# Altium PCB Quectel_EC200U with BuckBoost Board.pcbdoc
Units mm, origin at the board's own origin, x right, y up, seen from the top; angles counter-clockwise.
Board outline 58.96 x 62.7 mm, 2 copper layers (Top Layer, Bottom Layer); 75 components, 67 nets, 368 pads, 218 vias.
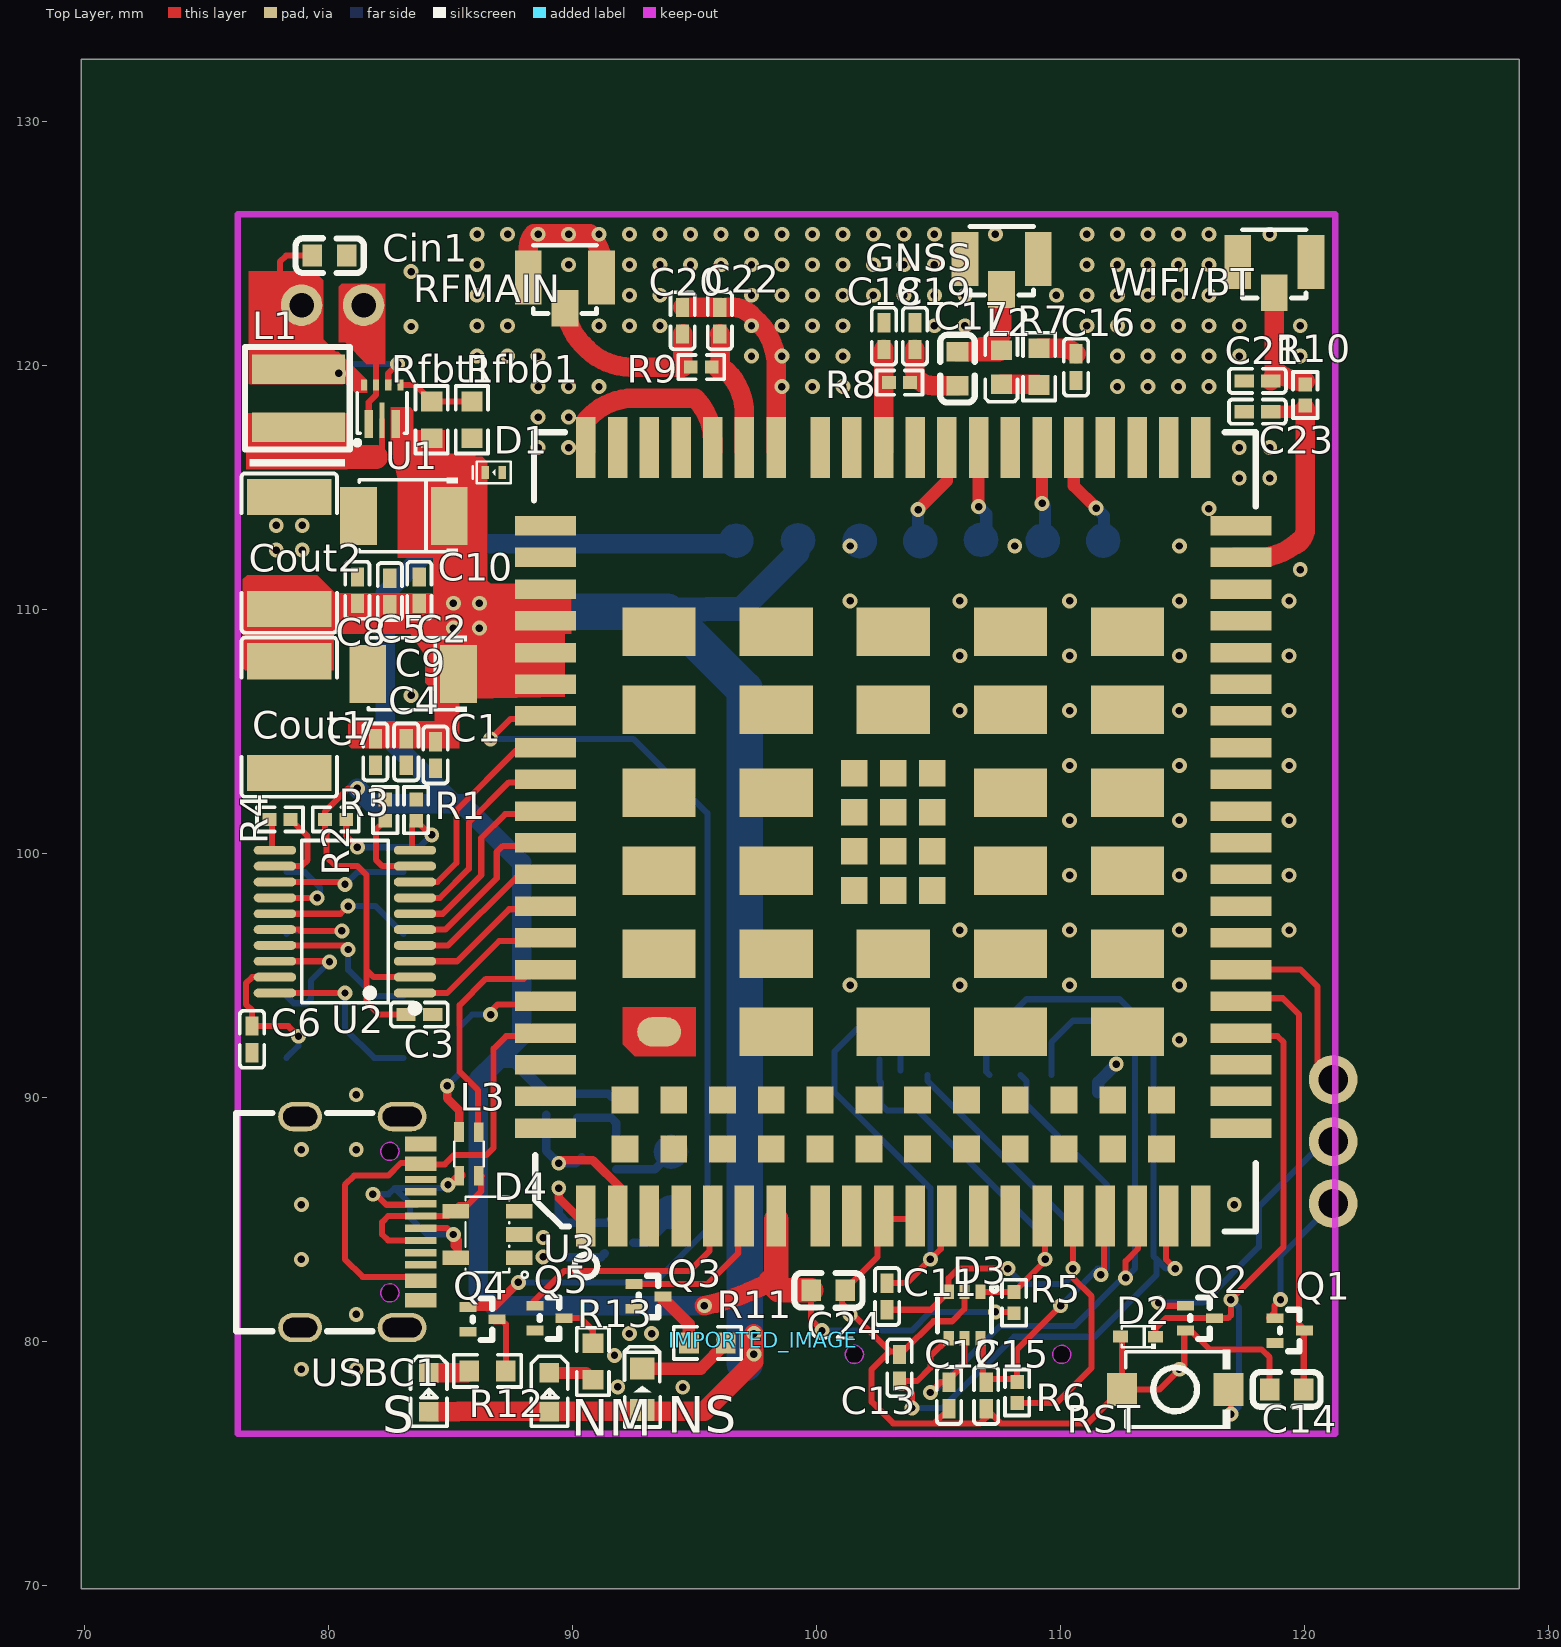
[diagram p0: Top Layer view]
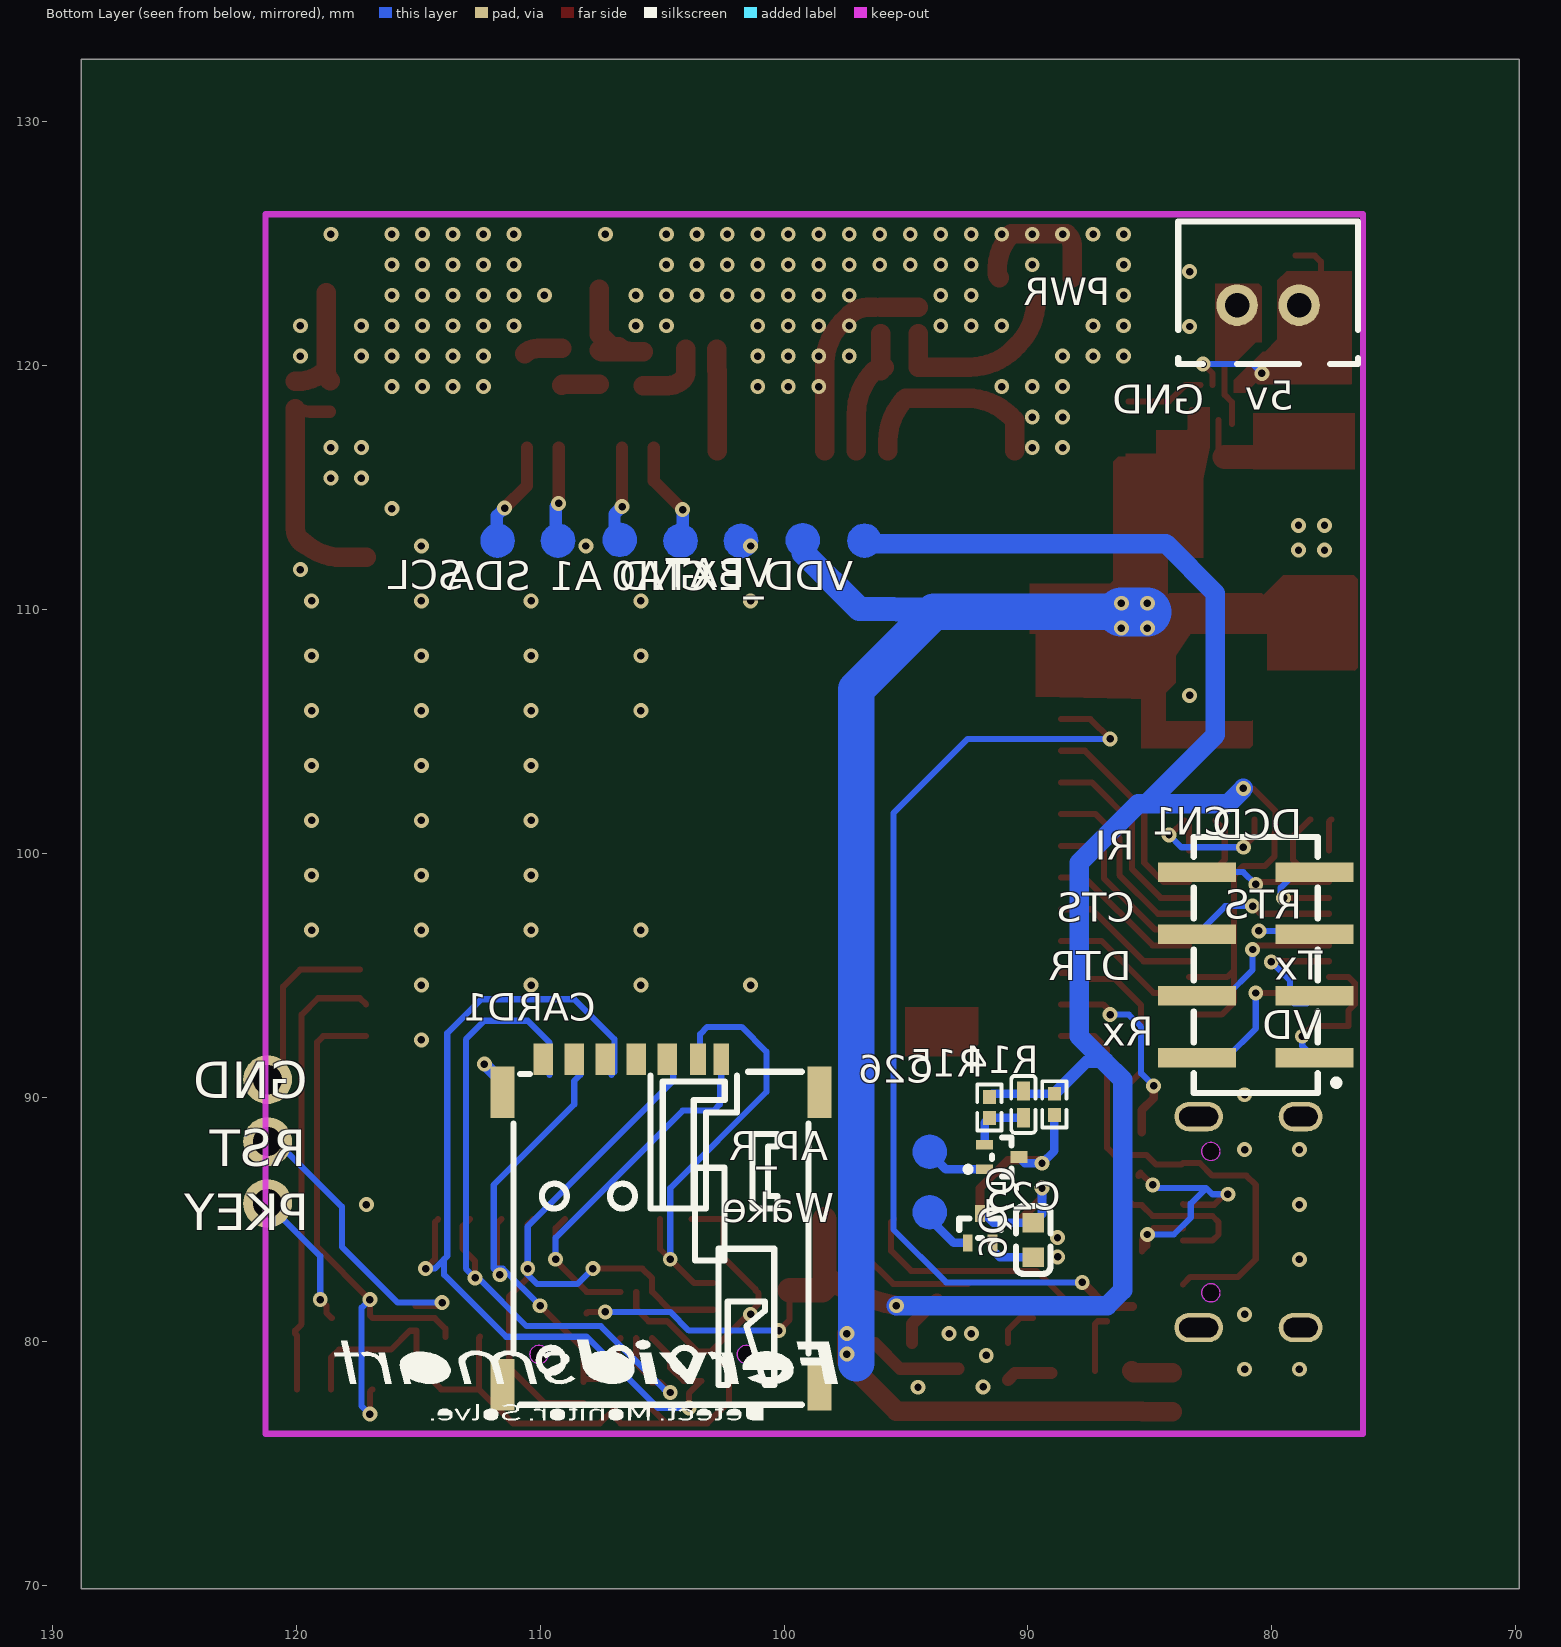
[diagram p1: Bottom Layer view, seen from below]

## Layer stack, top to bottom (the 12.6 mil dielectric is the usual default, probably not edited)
Top Layer: signal copper (thickness not stored)
Dielectric: dielectric 0.32, FR-4, Dk 4.8
Bottom Layer: signal copper (thickness not stored)

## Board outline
128.808,69.85 69.85,69.85 69.85,132.55 128.808,132.55

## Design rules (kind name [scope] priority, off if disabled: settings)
BoardOutlineClearance Default [All] p0: genericclearance=0.254 ignorepadtopadclearanceinfootprint=FALSE except(0: Arc-SplitContinuation Track-SplitContinuation SMDPad-SplitContinuation THPad-SplitContinuation Via-SplitContinuation Fill-SplitContinuation Poly-SplitContinuation Region-SplitContinuation Text-SplitContinuation; 0.152: Track-OutlineEdge SMDPad-OutlineEdge THPad-OutlineEdge Via-OutlineEdge Fill-OutlineEdge Region-OutlineEdge Poly-OutlineEdge Text-OutlineEdge Track-CutoutEdge SMDPad-CutoutEdge THPad-CutoutEdge Via-CutoutEdge Fill-CutoutEdge Region-CutoutEdge)
Clearance Default [(InNet('GND') OR InNet('VBAT') OR InNet('RSTKEY') OR InNet('PWRKEY') OR InNet('$1N59') OR InNet('RF_ANT') OR InNet('WIFI/BT_ANT') OR InNet('$1N62') OR InNet('GNSS_ANT') OR InNet('$1N42256') OR InNet('$1N42254') OR InNet('VDD_EXT') OR InNet('SIM_VDD') OR InNet('SIM_GND') OR InNet('VCC(5V)') OR InNet('WAKEUP_IN') OR InNet('AP_READY') OR InNet('PKEY') OR InNet('MCU_DTR') OR InNet('MCU_RTS') OR InNet('MCU_CTS') OR InNet('MCU_DCD') OR InNet('MCU_RI') OR InNet('$1N67') OR InNet('$3N3620') OR InNet('$3N3623') OR InNet('USB_DP') OR InNet('USB_DM') OR InNet('$1N56747') OR InNet('$3N512') OR InNet('RKEY') OR InNet('NW') OR InNet('STATUS') OR InNet('NW_MODE') OR InNet('SLEEP_IND') OR InNet('SIM_DATA') OR InNet('SIM_CLK') OR InNet('SIM_RST') OR InNet('$1N42291') OR InNet('$1N42271') OR InNet('$1N42272') OR InNet('ADC1') OR InNet('ADC0') OR InNet('I2C_SCL') OR InNet('I2C_SDA') OR InNet('$3N5937') OR InNet('$1N56691') OR InNet('MAIN_DCD') OR InNet('MAIN_RI') OR InNet('MAIN_DTR') OR InNet('MAIN_RXD') OR InNet('MAIN_TXD') OR InNet('MAIN_CTS') OR InNet('MAIN_RTS') OR InNet('MCU_TXD') OR InNet('MCU_RXD') OR InNet('MCC_VDD') OR InNet('$1N68') OR InNet('SIM_DET') OR InNet('$3N12540') OR InNet('$3N12543') OR InNet('VBUS') OR InNet('$3N13600') OR InNet('WAKEUP_IN_MCU') OR InNet('AP_READY_MCU') OR InNet('$3N15666') OR InNet('$3N15711'))] p1: gap=0.178 ignorepadtopadclearanceinfootprint=FALSE except(0: Poly-Poly; 0.152: Track-Track Track-SMDPad SMDPad-SMDPad Track-THPad SMDPad-THPad THPad-THPad Track-Via SMDPad-Via THPad-Via Via-Via Track-Fill SMDPad-Fill THPad-Fill Via-Fill Fill-Fill Track-Region SMDPad-Region THPad-Region Via-Region Fill-Region Region-Region Track-Poly SMDPad-Poly THPad-Poly Via-Poly Fill-Poly Region-Poly Track-Text SMDPad-Text THPad-Text Via-Text Fill-Text Region-Text Poly-Text Text-Text Track-Sheet SMDPad-Sheet THPad-Sheet Via-Sheet Fill-Sheet Region-Sheet Poly-Sheet Text-Sheet Track-Hole SMDPad-Hole THPad-Hole Via-Hole Fill-Hole Region-Hole Poly-Hole Text-Hole Sheet-Hole)
DiffPairsRouting differentialPair [All] p1: maxuncoupledlength=10 minlimit=5.9843 maxlimit=5.9843 mostfreqgap=5.9843 toplayer_minwidth=5 toplayer_prefwidth=10 toplayer_maxwidth=100 bottomlayer_minwidth=5 bottomlayer_prefwidth=10 bottomlayer_maxwidth=100
PasteMaskExpansion Common [All] p1: expansion=0
PlaneConnect Default [All] p1: planeconnectstyle=Relief reliefexpansion=0.508 reliefentries=4 reliefconductorwidth=0 reliefairgap=0.254
PolygonConnect copperRegion [All] p1: connectstyle=Direct reliefentries=4 reliefconductorwidth=10 polygonreliefangle="90 Angle" airgapwidth=10
PolygonConnect RF_copperRegion [All] p1: connectstyle=Direct reliefentries=4 reliefconductorwidth=10 polygonreliefangle="90 Angle" airgapwidth=10
RoutingVias Default [All] p1: viastyle="Through Hole" holewidth=12.0078 minholewidth=12.0078 maxholewidth=2362.0078 width=24.0158 minwidth=24.0158 maxwidth=3937.9922
SolderMaskExpansion Common [All] p1: useseparateexpansions=TRUE expansion=2.0079 expansionbottom=2.0079
Width Default [All] p1: maxlimit=236 minlimit=8 preferedwidth=10

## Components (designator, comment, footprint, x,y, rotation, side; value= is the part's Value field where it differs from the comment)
C1 "" C0402 84.369,104.03 r270 top
C2 "" C0402 83.707,110.786 r90 top
C3 "" C0402 83.707,93.387 r180 top
C4 "" C0402 83.172,104.155 r270 top
C5 "" C0402 82.498,110.733 r90 top
C6 "" C0402 76.849,92.371 r270 top
C7 "" C0402 81.904,104.155 r270 top
C8 "" C0402 81.167,110.786 r90 top
C9 "" CASE-B_3528 83.453,107.357 r180 top
C10 "" CASE-B_3528 83.072,113.834 r180 top
C11 "" C0402 102.884,81.83 r90 top
C12 "" C0402 105.424,77.766 r90 top
C13 "" C0402 103.392,78.909 r270 top
C14 "" C0603 119.267,78.02 r0 top
C15 "" C0402 106.948,77.766 r90 top
C16 "" C0402 110.631,119.93 r90 top
C17 "" C0603 105.77,119.867 r270 top
C18 "" C0402 102.757,121.2 r90 top
C19 "" C0402 104.027,121.2 r90 top
C20 "" C0402 94.502,121.835 r270 top
C21 "" C0402 118.068,119.369 r0 top
C22 "" C0402 96.026,121.835 r270 top
C23 "" C0402 118.068,118.104 r0 top
C24 "" C0603 100.471,82.084 r180 top
C25 "" C0603 89.781,84.145 r90 bottom
C26 "" C0402 90.184,89.704 r270 bottom
CARD1 "" SIM-SMD_SMN-303 105.043,84.878 r180 bottom
Cin1 "" C0603 80.024,124.502 r180 top
CN1 "" HDR-SMD_8P-P2.54-V-F-R2-C4-S7.1 80.659,95.419 r90 bottom
Cout1 "" C1812 78.373,105.579 r90 top
Cout2 "" C1812 78.373,112.31 r270 top
D1 "" X2SON-2_L1.0-W0.6-P0.70-RD 86.755,115.612 r0 top
D2 "" SOD-523F_L1.2-W0.8-LS1.7-RD 113.171,80.179 r180 top
D3 "" SC-70-6_L2.2-W1.3-P0.65-LS2.1-BR 106.059,81.068 r90 top
D4 "" SOT-23-5_L3.0-W1.7-P0.95-LS2.8-BR 86.501,84.37 r0 top
GNSS "" ANT-SMD_UFL-R-SMT-1-10 107.583,123.74 r90 top
IMPORTED_IMAGE "IMPORTED_IMAGE" IMPORTED_IMAGE 97.804,80.052 r0 top
L1 "" IND-SMD_L4.0-W4.0_XFL4020-102MEB 78.754,118.66 r270 top
L2 "47nH" IND-SMD_L1.6-W0.8-1 107.583,119.93 r90 top
L3 "" IND-SMD_4P-L2.0-W1.2-TL 85.739,87.672 r90 top
NM "" LED0603-RD 89.041,77.893 r270 top
NS "LED-0603_G" LED0603_GREEN 92.851,78.02 r90 top
PWR "" CONN-TH_B2B-XH-A-LF-SN 80.151,122.47 r180 bottom
Q1 "" SOT-416_L1.6-W0.8-P1.00-LS1.6-BR 119.394,80.433 r180 top
Q2 "" SOT-416_L1.6-W0.8-P1.00-LS1.6-BR 115.711,80.941 r180 top
Q3 "" SOT-416_L1.6-W0.8-P1.00-LS1.6-BR 93.105,81.83 r180 top
Q4 "" SOT-416_L1.6-W0.8-P1.00-LS1.6-BR 86.294,80.891 r180 top
Q5 "" SOT-416_L1.6-W0.8-P1.00-LS1.6-BR 89.041,80.941 r180 top
Q6 "" SOT-416_L1.6-W0.8-P1.00-LS1.6-BR 91.962,84.624 r270 bottom
Q7 "" SOT-416F_L1.6-W0.8-P1.00-LS1.6-TR 91.073,87.545 r0 bottom
R1 "" R0402 83.58,101.769 r90 top
R2 "" R0402 80.278,101.388 r180 top
R3 "" R0402 82.31,101.769 r270 top
R4 "" R0402 77.992,101.388 r180 top
R5 "" R0402 108.091,81.576 r90 top
R6 "" R0402 108.218,77.893 r90 top
R7 "" R0603 109.115,119.95 r270 top
R8 "" R0402 103.392,119.295 r180 top
R9 "" R0402 95.264,119.93 r180 top
R10 "" R0402 120.029,118.787 r90 top
R11 "100Ω" R0603 95.518,79.925 r180 top
R12 "100Ω" R0603 86.501,78.782 r0 top
R13 "" R0603 90.819,79.163 r270 top
R14 "" R0402 88.914,89.704 r90 bottom
R15 "" R0402 91.581,89.577 r270 bottom
Rfbb1 "" R0603 85.866,117.771 r90 top
Rfbt1 "" R0603 84.215,117.771 r270 top
RFMAIN "" ANT-SMD_UFL-R-SMT-1-10 89.676,122.978 r90 top
RST "" SW-SMD_L3.9-W3.0-P4.45 114.695,78.02 r0 top
S "" LED0603-RD 84.088,77.893 r270 top
U1 "" VQFN-7_L2.0-W2.0-P0.55-TL_RWU 82.183,118.406 r90 top
U2 "" TSSOP-20_L6.5-W4.4-P0.65-LS6.4-BL 80.659,97.197 r90 top
U3 "" LCC-LGA-144_L32.0-W29.0-CAT1-CUIOT-MZ-6 103.138,100.88 r90 top
USBC1 "" USB-C_SMD-TYPE-C-31-M-12 81.294,84.878 r270 top
WIFI/BT "" ANT-SMD_UFL-R-SMT-1-10 118.759,123.613 r90 top

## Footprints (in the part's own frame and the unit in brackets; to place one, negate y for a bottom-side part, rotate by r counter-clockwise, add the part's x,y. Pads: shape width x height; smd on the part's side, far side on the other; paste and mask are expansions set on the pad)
ANT-SMD_UFL-R-SMT-1-10 [mm]
  rect 2.2x1.1 smd: 1(0.625,1.5) 3(0.625,-1.5)
  rect 1.5x1.1 smd: 2(-0.625,0.001)
  silkscreen extent -0.85,-1.3 1.95,1.3
C0402 [mm]
  rect 0.79x0.54 smd: 1(-0.545,0) 2(0.545,0)
  silkscreen extent -1.17,-0.5 1.17,0.5
C0603 [mm]
  rect 0.8x0.9 smd: 1(-0.7,0) 2(0.7,0)
  silkscreen extent -1.39,-0.71 1.39,0.71
C1812 [mm]
  rect 1.485x3.456 smd: 1(-2.293,0) 2(2.293,0)
  silkscreen extent -3.26,-1.96 3.26,1.96
CASE-B_3528 [mm]
  rect 1.506x2.376 smd: 1(-1.861,0) 2(1.861,0)
  silkscreen extent -2.21,-1.55 1.83,1.55
CONN-TH_B2B-XH-A-LF-SN [mm]
  round 1.7 hole 1: 1(1.27,0) 2(-1.27,0)
  silkscreen extent -3.68,-2.41 3.68,3.43
HDR-SMD_8P-P2.54-V-F-R2-C4-S7.1 [mm]
  rect 0.8x3.2 smd: 1(-3.81,-2.4) 2(-3.81,2.4) 3(-1.27,-2.4) 4(-1.27,2.4) 5(1.27,-2.4) 6(1.27,2.4) 7(3.81,-2.4) 8(3.81,2.4)
  silkscreen extent -5.25,-3.43 5.25,2.54
IMPORTED_IMAGE [mm]
IND-SMD_4P-L2.0-W1.2-TL [mm]
  rect 0.8x0.4 smd: 1(-0.901,0.399) 2(-0.899,-0.4) 3(0.9,-0.4) 4(0.901,0.4)
  silkscreen extent -0.5,-0.6 0.5,0.6
IND-SMD_L1.6-W0.8-1 [mm]
  rect 0.8x0.864 smd: 1(0.7,0) 2(-0.7,0)
  silkscreen extent -1.42,-0.65 1.41,0.67
IND-SMD_L4.0-W4.0_XFL4020-102MEB [mm]
  rect 1.2x3.8 smd: 1(-1.189,0) 2(1.189,0)
  silkscreen extent -2.1,-2.2 2.8,2.1
LCC-LGA-144_L32.0-W29.0-CAT1-CUIOT-MZ-6 [mm]
  rect 2.5x0.8 smd: 1(-15.75,12.6) 2(-15.75,11.3) 3(-15.75,10) 4(-15.75,8.7) 5(-15.75,7.4) 6(-15.75,6.1) 7(-15.75,4.8) 8(-15.75,0.4) 9(-15.75,-0.9) 10(-15.75,-2.2) 11(-15.75,-3.5) 12(-15.75,-4.8) 13(-15.75,-6.1) 14(-15.75,-7.4) 15(-15.75,-8.7) 16(-15.75,-10) 17(-15.75,-11.3) 18(-15.75,-12.6) 37(15.75,-12.6) 38(15.75,-11.3) 39(15.75,-10) 40(15.75,-8.7) 41(15.75,-7.4) 42(15.75,-6.1) 43(15.75,-4.8) 44(15.75,-3.5) 45(15.75,-2.2) 46(15.75,-0.9) 47(15.75,0.4) 48(15.75,4.8) 49(15.75,6.1) 50(15.75,7.4) 51(15.75,8.7) 52(15.75,10) 53(15.75,11.3) 54(15.75,12.6) 141(-15.75,3) 142(-15.75,1.7) 143(15.75,1.7) 144(15.75,3)
  rect 0.8x2.5 smd: 19(-9.55,-14.25) 20(-8.25,-14.25) 21(-6.95,-14.25) 22(-5.65,-14.25) 23(-4.35,-14.25) 24(-3.05,-14.25) 25(-1.75,-14.25) 26(-0.45,-14.25) 27(0.85,-14.25) 28(2.15,-14.25) 29(3.45,-14.25) 30(4.75,-14.25) 31(6.05,-14.25) 32(7.35,-14.25) 33(8.65,-14.25) 34(9.95,-14.25) 35(11.25,-14.25) 36(12.55,-14.25) 55(12.55,14.25) 56(11.25,14.25) 57(9.95,14.25) 58(8.65,14.25) 59(7.35,14.25) 60(6.05,14.25) 61(4.75,14.25) 62(3.45,14.25) 63(2.15,14.25) 64(0.85,14.25) 65(-0.45,14.25) 66(-1.75,14.25) 67(-3.05,14.25) 68(-4.35,14.25) 69(-5.65,14.25) 70(-6.95,14.25) 71(-8.25,14.25) 72(-9.55,14.25) 113(-10.85,14.25) 114(-12.15,14.25) 115(-10.85,-14.25) 116(-12.15,-14.25)
  rect 1.1x1.1 smd: 73(2.4,1.6) 74(2.4,0) 75(2.4,-1.6) 76(0.8,1.6) 77(0.8,0) 78(0.8,-1.6) 79(-0.8,1.6) 80(-0.8,0) 81(-0.8,-1.6) 82(-2.4,1.6) 83(-2.4,0) 84(-2.4,-1.6) 117(-11,11) 118(-11,9) 119(-11,7) 120(-11,5) 121(-11,3) 122(-11,1) 123(-11,-1) 124(-11,-3) 125(-11,-5) 126(-11,-7) 127(-11,-9) 128(-11,-11) 129(-13,11) 130(-13,9) 131(-13,7) 132(-13,5) 133(-13,3) 134(-13,1) 135(-13,-1) 136(-13,-3) 137(-13,-5) 138(-13,-7) 139(-13,-9) 140(-13,-11)
  rect 2x3 smd: 85(8.2,9.6) 86(8.2,4.8) 87(8.2,0) 88(8.2,-4.8) 89(8.2,-9.6) 90(5,9.6) 91(5,4.8) 92(5,0) 93(5,-4.8) 94(5,-9.6) 95(1.6,9.6) 96(1.6,4.8) 97(1.6,-4.8) 98(1.6,-9.6) 99(-1.6,9.6) 100(-1.6,4.8) 101(-1.6,-4.8) 102(-1.6,-9.6) 103(-5,9.6) 104(-5,4.8) 105(-5,0) 106(-5,-4.8) 107(-5,-9.6) 109(-8.2,4.8) 110(-8.2,0) 111(-8.2,-4.8) 112(-8.2,-9.6)
  oval 1.2x1.8 smd: 108(-8.2,9.6)
  Top Layer region: -9.2,8.1 -7.2,8.1 -7.2,11.1 -8.7,11.1 -9.2,10.6
  silkscreen extent -18.26,-14.86 16.38,14.73
LED0603-RD [mm]
  rect 0.8x0.8 smd: 1(-0.799,0) 2(0.799,0)
  silkscreen extent -1.49,-0.75 1.39,0.76
LED0603_GREEN [mm]
  rect 0.9x1 smd: 1(-0.85,0) 2(0.85,0)
  silkscreen extent -1.54,-0.73 1.75,0.73
R0402 [mm]
  rect 0.566x0.54 smd: 1(-0.433,0) 2(0.433,0)
  silkscreen extent -0.94,-0.5 0.94,0.5
R0603 [mm]
  rect 0.806x0.864 smd: 1(-0.753,0) 2(0.753,0)
  silkscreen extent -1.39,-0.66 1.39,0.66
SC-70-6_L2.2-W1.3-P0.65-LS2.1-BR [mm]
  rect 0.6x0.42 smd: 1(0.95,-0.65) 2(0.95,0) 3(0.95,0.65) 4(-0.95,0.65) 5(-0.95,0) 6(-0.95,-0.65)
  silkscreen extent -0.7,-1.34 1.22,1.1
SIM-SMD_SMN-303 [mm]
  rect 1x2.1 smd: 8(-6.5,5.328) 9(6.5,5.328) 10(6.5,-6.672) 11(-6.5,-6.672)
  rect 0.8x1.3 smd: C1(0.25,6.672) C2(-2.29,6.672) C3(-4.83,6.672) C6(-1.02,6.672) C7(-3.56,6.672)
  rect 0.65x1.3 smd: C5(1.52,6.672) CD(2.47,6.672)
  Board Outline Layer circle w0.005: c-5,-5.422 r0.375
  Board Outline Layer circle w0.005: c3.5,-5.422 r0.375
  Board Outline Layer region: -5.375,-5.422 -5.338,-5.585 -5.234,-5.715 -5.083,-5.788 -4.916,-5.788 -4.766,-5.715 -4.662,-5.585 -4.625,-5.422 -4.625,-5.422 -4.662,-5.259 -4.766,-5.129 -4.916,-5.057 -5.083,-5.057 -5.234,-5.129 -5.338,-5.259 -5.375,-5.422
  Board Outline Layer region: 3.125,-5.422 3.162,-5.585 3.266,-5.715 3.417,-5.788 3.583,-5.788 3.734,-5.715 3.838,-5.585 3.875,-5.422 3.875,-5.422 3.838,-5.259 3.734,-5.129 3.583,-5.057 3.417,-5.057 3.266,-5.129 3.162,-5.259 3.125,-5.422
  Multi-Layer board cut-out: -5.375,-5.422 -5.338,-5.585 -5.234,-5.715 -5.083,-5.788 -4.916,-5.788 -4.766,-5.715 -4.662,-5.585 -4.625,-5.422 -4.625,-5.422 -4.662,-5.259 -4.766,-5.129 -4.916,-5.057 -5.083,-5.057 -5.234,-5.129 -5.338,-5.259 -5.375,-5.422
  Multi-Layer board cut-out: 3.125,-5.422 3.162,-5.585 3.266,-5.715 3.417,-5.788 3.583,-5.788 3.734,-5.715 3.838,-5.585 3.875,-5.422 3.875,-5.422 3.838,-5.259 3.734,-5.129 3.583,-5.057 3.417,-5.057 3.266,-5.129 3.162,-5.259 3.125,-5.422
  silkscreen extent -6.04,-7.49 6.04,6.16
SOD-523F_L1.2-W0.8-LS1.7-RD [mil]
  rect 24x19 smd: 1(-28,0.2) 2(28,-0.2)
  silkscreen extent -29,-19 26,19
SOT-23-5_L3.0-W1.7-P0.95-LS2.8-BR [mm]
  rect 1.1x0.6 smd: 1(1.3,-0.95) 2(1.3,0) 3(1.3,0.95) 4(-1.3,0.95) 5(-1.3,-0.95)
  silkscreen extent -0.9,-1.78 1.65,1.55
SOT-416_L1.6-W0.8-P1.00-LS1.6-BR [mm]
  rect 0.7x0.4 smd: 1(0.6,-0.508) 2(0.6,0.508) 3(-0.6,0)
  silkscreen extent -0.4,-0.85 0.4,0.85
SOT-416F_L1.6-W0.8-P1.00-LS1.6-TR [mm]
  rect 0.7x0.4 smd: 1(0.7,0.5) 2(0.7,-0.5)
  rect 0.7x0.5 smd: 3(-0.7,0)
  silkscreen extent -0.4,-0.8 1.48,0.8
SW-SMD_L3.9-W3.0-P4.45 [mm]
  rect 1.23x1.36 smd: 1(-2.185,0) 2(2.185,0)
  silkscreen extent -2.03,-1.62 2.25,1.62
TSSOP-20_L6.5-W4.4-P0.65-LS6.4-BL [mm]
  oval 0.364x1.742 smd: 1(-2.925,-2.871) 2(-2.275,-2.871) 3(-1.625,-2.871) 4(-0.975,-2.871) 5(-0.325,-2.871) 6(0.325,-2.871) 7(0.975,-2.871) 8(1.625,-2.871) 9(2.275,-2.871) 10(2.925,-2.871) 11(2.925,2.871) 12(2.275,2.871) 13(1.625,2.871) 14(0.975,2.871) 15(0.325,2.871) 16(-0.325,2.871) 17(-0.975,2.871) 18(-1.625,2.871) 19(-2.275,2.871) 20(-2.925,2.871)
  silkscreen extent -3.71,-3.02 3.33,1.77
USB-C_SMD-TYPE-C-31-M-12 [mm]
  oval 1.2x2 hole 0.8 slot 1.6 at 90 deg: 0(-4.325,1.706) 1(4.325,1.706)
  oval 1.2x1.8 hole 0.8 slot 1.4 at 90 deg: 2(4.325,-2.474) 3(-4.325,-2.474)
  rect 0.3x1.3 smd: A1(-3.35,2.474) A4(-2.55,2.474) A5(-1.25,2.474) A6(-0.25,2.474) A7(0.25,2.474) A8(1.25,2.474) A9(2.55,2.474) A12(3.35,2.474) B1(3.05,2.474) B4(2.25,2.474) B5(1.75,2.474) B6(0.75,2.474) B7(-0.75,2.474) B8(-1.75,2.474) B9(-2.25,2.474) B12(-3.05,2.474)
  Board Outline Layer circle w0.005: c-2.9,1.206 r0.375
  Board Outline Layer circle w0.005: c2.9,1.206 r0.375
  Board Outline Layer region: -2.9,1.581 -2.737,1.544 -2.607,1.439 -2.534,1.289 -2.534,1.122 -2.607,0.972 -2.737,0.868 -2.9,0.831 -2.9,0.831 -3.063,0.868 -3.193,0.972 -3.266,1.122 -3.266,1.289 -3.193,1.439 -3.063,1.544 -2.9,1.581
  Board Outline Layer region: 2.9,1.581 3.063,1.544 3.193,1.439 3.266,1.289 3.266,1.122 3.193,0.972 3.063,0.868 2.9,0.831 2.9,0.831 2.737,0.868 2.607,0.972 2.534,1.122 2.534,1.289 2.607,1.439 2.737,1.544 2.9,1.581
  Multi-Layer board cut-out: -2.9,1.581 -2.737,1.544 -2.607,1.439 -2.534,1.289 -2.534,1.122 -2.607,0.972 -2.737,0.868 -2.9,0.831 -2.9,0.831 -3.063,0.868 -3.193,0.972 -3.266,1.122 -3.266,1.289 -3.193,1.439 -3.063,1.544 -2.9,1.581
  Multi-Layer board cut-out: 2.9,1.581 3.063,1.544 3.193,1.439 3.266,1.289 3.266,1.122 3.193,0.972 3.063,0.868 2.9,0.831 2.9,0.831 2.737,0.868 2.607,0.972 2.534,1.122 2.534,1.289 2.607,1.439 2.737,1.544 2.9,1.581
  silkscreen extent -4.47,-5.09 4.47,0.49
VQFN-7_L2.0-W2.0-P0.55-TL_RWU [mm]
  rect 1.15x0.35 smd: 1(-0.8,0.55) 3(-0.8,-0.55)
  rect 1.45x0.2 smd: 2(-0.65,0)
  rect 0.45x0.25 smd: 4(0.8,-0.75) 5(0.8,-0.25) 6(0.8,0.25) 7(0.8,0.75)
  silkscreen extent -1.67,-1.02 0.46,1.12
X2SON-2_L1.0-W0.6-P0.70-RD [mm]
  rect 0.3x0.55 smd: 1(-0.35,0) 2(0.35,0)
  silkscreen extent -0.85,-0.45 0.7,0.45

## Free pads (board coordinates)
  round 2 hole 1.2: 1(121.172,85.64) 1(121.172,88.18) 1(121.172,90.72)

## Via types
v1: diameter 0.61, hole 0.305, Top Layer to Bottom Layer, 218 vias

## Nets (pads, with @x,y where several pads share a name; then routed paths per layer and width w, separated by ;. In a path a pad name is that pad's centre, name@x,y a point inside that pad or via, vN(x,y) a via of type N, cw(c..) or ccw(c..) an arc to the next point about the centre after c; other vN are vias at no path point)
$1N59: C20.2 R9.2 RFMAIN.2 | length 7.7
  Top Layer w0.8: RFMAIN.2@89.675,122.634 ccw(c92.215,122.634) 90.419,120.838 90.583,120.674 ccw(c92.379,122.47) 92.379,119.93 94.502,119.93 C20.2
$1N62: C21.2 R10.2 WIFI/BT.2 | length 5.1
  Top Layer w0.8: C21.2 ccw(c118.262,119.719) 118.758,119.719 118.758,119.846 ; WIFI/BT.2 118.758,119.846 ; R10.2@120.029,119.347 119.964,119.347 cw(c119.964,121.052) 118.846,119.764 cw(c119.964,121.052) 118.758,119.846
$1N67: L2.2 R7.2 | length 1.5
  Top Layer w0.8: L2.2 109.034,119.23 cw(c109.034,119.115) R7.2
$1N68: C16.2 R7.1 | length 1.6
  Top Layer w0.8: R7.1 110.081,120.703 cw(c110.081,119.925) C16.2
$1N42254: C17.1 GNSS.2 L2.1 | length 5.2
  Top Layer w0.8: C17.1 106.28,120.567 ; GNSS.2 cw(c107.579,123.112) 107.583,123.112 107.583,121.283 107.071,120.772 106.774,120.772 cw(c106.28,121.266) 106.28,120.567 ; L2.1 cw(c107.432,120.781) 107.432,120.567 106.28,120.567
$1N42256: C17.2 C19.1 R8.1 | length 2.9
  Top Layer w0.8: C19.1 104.027,119.729 ccw(c104.461,119.729) 104.102,119.484 ccw(c104.461,119.729) 104.154,119.422 ccw(c104.767,120.035) 104.767,119.168 C17.2@105.768,119.168
$1N42271: R3.2 U2.9 | length 3.3
  Top Layer w0.25: R3.2 81.929,100.955 81.929,99.737 82.194,99.472 U2.9@83.403,99.472
$1N42272: R4.1 U2.12 | length 3.5
  Top Layer w0.25: U2.12@77.661,99.472 78.874,99.472 79.124,99.722 79.124,100.689 R4.1
$1N42291: R1.1 R2.1 U2.10 | length 6.8
  Top Layer w0.25: R2.1 80.711,100.701 v1(81.167,100.245) ; U2.10@83.403,100.122 83.403,101.159 R1.1 84.163,100.753 v1(84.215,100.753)
  Bottom Layer w0.25: v1(81.167,100.245) 83.707,100.245 v1(84.215,100.753)
$1N56691: Rfbb1.2 Rfbt1.1 U1.4 | length 3.2
  Top Layer w0.25: U1.4 83.533,119.206 Rfbt1.1 Rfbb1.2
$1N56747: L1.2 U1.2 | length 5.3
  Top Layer w0.25: 81.929,116.247 82.183,116.501 U1.2
  Top Layer w1: L1.2 79.978,116.247 81.929,116.247
$3N512: R12.1 S.1 | length 1.7
  Top Layer w0.8: S.1 85.658,78.692 R12.1
$3N3620: D4.5 L3.1 USBC1.A7 USBC1.B7 | length 12.8
  Top Layer w0.25: v1(81.802,86.021) 81.929,86.021 82.36,85.59 83.603,85.59 USBC1.B7@83.641,85.628 ; USBC1.A7@83.641,84.628 84.846,84.628 v1(85.104,84.37) ; v1(84.882,86.402) 85.386,86.906 85.467,86.825 L3.1@85.467,86.771 ; v1(85.104,84.37) 85.104,83.898 85.328,83.674 85.328,84.146 v1(85.104,84.37)
  Bottom Layer w0.25: v1(81.802,86.021) 82.437,86.021 82.691,86.275 ; v1(84.882,86.402) 84.755,86.275 82.691,86.275 ; v1(85.104,84.37) 84.017,84.37 83.326,85.061 83.326,85.64 82.691,86.275
$3N3623: D4.4 L3.2 USBC1.A6 USBC1.B6 | length 7.3
  Top Layer w0.25: USBC1.B6@83.641,84.128 82.425,84.128 82.183,84.37 82.183,84.878 82.433,85.128 USBC1.A6 84.882,85.128 85.328,85.574 85.673,85.574 86.247,86.148 86.247,86.754 L3.2@86.266,86.773
$3N5937: NM.1 R13.2 | length 1.9
  Top Layer w0.5: NM.1 90.536,78.692 R13.2
$3N12540: NS.2 R11.1 | length 3.9
  Top Layer w0.5: NS.2 95.245,78.87 96.271,79.896 R11.1
$3N12543: Q3.3 R11.2 | length 2.2
  Top Layer w0.5: Q3.3@93.705,81.703 93.749,81.703 94.756,80.696 R11.2@94.756,79.916
$3N13600: C26.2 Q7.2 R15.2 | length 2.6
  Bottom Layer w0.35: C26.2 91.566,89.159 R15.2 91.773,88.952 Q7.2
$3N15666: Q4.3 R12.2 | length 2.5
  Top Layer w0.25: Q4.3@86.764,80.814 87.136,80.814 87.254,80.696 R12.2
$3N15711: Q5.3 R13.1 | length 1.8
  Top Layer w0.25: Q5.3@89.794,80.941 90.326,80.941 90.819,80.448 R13.1
ADC0: U3.45 | length 4.6
  Top Layer w0.5: v1(104.154,114.088) 105.338,115.272 U3.45
  Bottom Layer w0.5: 104.154,112.564 v1(104.154,114.088)
ADC1: U3.44 | length 3.9
  Top Layer w0.5: v1(106.638,114.215) U3.44
  Bottom Layer w0.5: v1(106.638,114.215) 106.948,113.905 106.948,112.818
AP_READY: Q7.3 R14.1 U3.2 | length 7.7
  Top Layer w0.35: v1(89.422,87.291) 89.549,87.418 90.819,87.418 91.965,86.272 91.965,85.384 U3.2@91.584,85.003
  Bottom Layer w0.35: R14.1 88.914,87.799 v1(89.422,87.291) 90.119,87.291 Q7.3
AP_READY_MCU: Q7.1 | length 2.5
  Bottom Layer w0.35: Q7.1 93.367,87.045 93.994,87.672
GND: C1.2 C2.2 C3.1 C4.2 C5.2 C6.2 C7.2 C8.2 C9.2 C10.2 C12.1 C13.1 C14.1 C15.1 C16.1 C18.2 C19.2 C20.1 C21.1 C22.1 C23.1 C24.1 C25.1 CARD1.8 CARD1.9 CARD1.10 CARD1.11 Cin1.1 Cout1.1 Cout2.1 D1.2 D2.2 D3.2 D4.1 D4.2 D4.3 GNSS.1 GNSS.3 pad.1@121.172,90.72 PWR.2 Q1.2 Q2.2 Q3.2 Q4.2 Q5.2 Q6.2 R1.2 R3.1 R4.2 Rfbb1.1 RFMAIN.1 RFMAIN.3 RST.1 U1.1 U1.6 U2.11 U3.8 U3.9 U3.19 U3.22 U3.36 U3.46 U3.48 U3.50 U3.51 U3.52 U3.53 U3.54 U3.56 U3.72 U3.76 U3.85 U3.86 U3.87 U3.88 U3.89 U3.90 U3.91 U3.92 U3.93 U3.94 U3.95 U3.96 U3.97 U3.98 U3.99 U3.100 U3.101 U3.102 U3.103 U3.104 U3.105 U3.106 U3.107 U3.108 U3.109 U3.110 U3.111 U3.112 USBC1.A1 USBC1.A12 USBC1.B1 USBC1.B12 WIFI/BT.1 WIFI/BT.3 | length 79.6
  Top Layer w0.25: R4.2 77.661,101.286 U2.11@77.661,100.122 ; PWR.2 81.933,121.958 U1.6 81.933,118.791 81.633,118.491 U1.1 ; C13.1 C13.1@103.392,79.579 ; U3.9@103.784,85.003 102.484,85.003 102.484,83.447 101.171,82.134 C24.1 101.044,81.957 101.044,81.526 102.991,79.579 ; C12.1 104.826,76.623 ; D3.2 106.059,81.322 105.551,80.814 104.789,80.814 103.554,79.579 C13.1@103.392,79.579 ; D2.2 112.51,80.134 RST.1 ; U3.22 119.837,95.23 120.537,94.53 120.537,91.355 120.984,90.908 pad.1@120.984,90.72 ; C14.1 118.567,79.331 118.242,79.656 116.107,79.656 115.339,80.424 115.067,80.424 115.067,79.027 114.06,78.02 RST.1 ; 102.991,79.579 C13.1@103.392,79.579 ; 102.991,79.579 102.249,78.837 102.249,77.512 103.138,76.623 104.826,76.623 ; 104.826,76.623 106.698,76.623 106.948,76.873 C15.1 107.546,76.623 111.113,76.623 RST.1
  Top Layer w0.8: RFMAIN.1 88.176,124.836 cw(c88.961,124.836) 88.249,125.167 cw(c88.961,124.836) 88.406,125.391 90.692,125.391 cw(c89.054,123.913) 90.786,125.279 cw(c89.054,123.913) 90.84,125.209 cw(c89.054,123.913) 91.258,123.8 cw(c90.979,123.8) RFMAIN.3 ; U3.54@90.538,116.503 90.538,117.705 cw(c90.631,117.705) 90.565,117.771 90.71,117.916 cw(c92.506,116.12) 90.94,118.12 cw(c92.506,116.12) 91.768,118.55 cw(c92.506,116.12) 92.506,118.66 95.01,118.66 cw(c93.253,116.903) 95.148,118.511 cw(c93.253,116.903) 95.738,116.903 U3.50@95.738,116.503 ; C20.1 C22.1 ; C22.1@96.28,122.38 96.593,122.38 cw(c96.593,121.386) 97.296,122.089 97.594,121.791 cw(c95.798,119.995) 97.623,121.762 cw(c95.798,119.995) 97.992,121.275 cw(c95.798,119.995) 98.183,120.867 cw(c95.798,119.995) 98.296,120.455 cw(c95.798,119.995) 98.311,120.361 cw(c95.798,119.995) 98.338,119.995 U3.48@98.338,116.503
  Bottom Layer w0.35: C25.1 91.158,83.445 91.312,83.599
  Bottom Layer w0.5: CARD1.8 111.543,90.616 v1(112.282,91.355)
  other v1: 94.506,78.106 91.84,78.125 78.869,78.848 81.119,78.848 114.869,78.848 91.708,79.417 92.32,80.306 93.232,80.306 81.119,81.098 101.369,81.098 78.869,83.348 88.78,83.449 88.787,84.243 78.869,85.598 117.119,85.598 78.869,87.848 81.119,87.848 81.119,90.098 114.869,92.348 101.369,94.598 105.869,94.598 110.369,94.598 114.869,94.598 105.869,96.848 110.369,96.848 114.869,96.848 119.369,96.848 110.369,99.098 114.869,99.098 119.369,99.098 110.369,101.348 114.869,101.348 119.369,101.348 110.369,103.598 114.869,103.598 119.369,103.598 105.869,105.848 110.369,105.848 114.869,105.848 119.369,105.848 83.369,106.47 105.869,108.098 110.369,108.098 114.869,108.098 119.369,108.098 101.369,110.348 105.869,110.348 110.369,110.348 114.869,110.348 119.369,110.348 119.825,111.63 77.84,112.427 78.907,112.427 101.369,112.598 108.119,112.598 114.869,112.598 77.84,113.443 78.907,113.443 116.075,114.13 117.325,115.38 118.575,115.38 88.575,116.63 89.825,116.63 117.325,116.63 118.575,116.63 88.575,117.88 89.825,117.88 88.575,119.13 89.825,119.13 91.075,119.13 98.575,119.13 99.825,119.13 101.075,119.13 112.325,119.13 113.575,119.13 114.825,119.13 116.075,119.13 86.075,120.38 87.325,120.38 88.575,120.38 97.325,120.38 98.575,120.38 99.825,120.38 101.075,120.38 112.325,120.38 113.575,120.38 114.825,120.38 116.075,120.38 117.325,120.38 119.825,120.38 83.369,121.598 86.075,121.63 87.325,121.63 91.075,121.63 92.325,121.63 93.575,121.63 97.325,121.63 98.575,121.63 99.825,121.63 101.075,121.63 104.825,121.63 106.075,121.63 111.075,121.63 112.325,121.63 113.575,121.63 114.825,121.63 116.075,121.63 117.325,121.63 119.825,121.63 86.075,122.88 92.325,122.88 93.575,122.88 97.325,122.88 98.575,122.88 99.825,122.88 101.075,122.88 102.325,122.88 103.575,122.88 104.825,122.88 106.075,122.88 109.825,122.88 111.075,122.88 112.325,122.88 113.575,122.88 114.825,122.88 116.075,122.88 83.369,123.848 86.075,124.13 89.825,124.13 92.325,124.13 93.575,124.13 94.825,124.13 96.075,124.13 97.325,124.13 98.575,124.13 99.825,124.13 101.075,124.13 102.325,124.13 103.575,124.13 104.825,124.13 111.075,124.13 112.325,124.13 113.575,124.13 114.825,124.13 116.075,124.13 86.075,125.38 87.325,125.38 88.575,125.38 89.825,125.38 91.075,125.38 92.325,125.38 93.575,125.38 94.825,125.38 96.075,125.38 97.325,125.38 98.575,125.38 99.825,125.38 101.075,125.38 102.325,125.38 103.575,125.38 104.825,125.38 107.325,125.38 111.075,125.38 112.325,125.38 113.575,125.38 114.825,125.38 116.075,125.38 118.575,125.38
GNSS_ANT: C18.1 R8.2 U3.47 | length 4.2
  Top Layer w0.8: U3.47@102.738,116.503 102.738,119.784 102.757,119.803 C18.1
I2C_SCL: U3.41 | length 4.5
  Top Layer w0.5: U3.41 110.538,115.07 v1(111.457,114.151)
  Bottom Layer w0.5: v1(111.457,114.151) 111.774,113.834 111.774,112.691
I2C_SDA: U3.42 | length 3.7
  Top Layer w0.5: v1(109.238,114.342) U3.42
  Bottom Layer w0.5: v1(109.238,114.342) 109.361,114.219 109.361,112.945
MAIN_CTS: U2.6 U3.64 | length 7.8
  Top Layer w0.25: U2.6@83.403,97.522 84.667,97.522 86.247,99.102 86.247,100.626 87.224,101.603 U3.64@88.634,101.603
MAIN_DCD: U2.7 U3.63 | length 8.3
  Top Layer w0.25: U2.7@83.403,98.172 84.555,98.172 85.739,99.356 85.739,101.261 87.381,102.903 U3.63@88.634,102.903
MAIN_DTR: U2.4 U3.66 | length 6.4
  Top Layer w0.25: U2.4@83.403,96.222 84.891,96.222 87.672,99.003 U3.66@88.634,99.003
MAIN_RI: U2.8 U3.62 | length 8.7
  Top Layer w0.25: U2.8@83.403,98.822 84.443,98.822 85.231,99.61 85.231,101.769 87.665,104.203 U3.62@88.634,104.203
MAIN_RTS: U2.5 U3.65 | length 7.3
  Top Layer w0.25: U2.5@83.403,96.872 84.779,96.872 86.882,98.975 86.882,100.053 87.132,100.303 U3.65@88.634,100.303
MAIN_RXD: U2.1 U3.68 | length 6.1
  Top Layer w0.25: U2.1@83.403,94.272 84.846,94.272 86.977,96.403 U3.68@88.634,96.403
MAIN_TXD: U2.3 U3.67 | length 6.1
  Top Layer w0.25: U2.3@83.403,95.572 85.257,95.572 87.388,97.703 U3.67@88.634,97.703
MCC_VDD: C6.1 CN1.1 U2.19 | length 6.2
  Top Layer w0.25: U2.19@77.661,94.922 76.849,94.922 76.599,94.672 76.599,93.811 76.849,93.561 C6.1 78.336,92.916 v1(78.754,92.498)
  Bottom Layer w0.25: CN1.1 78.754,92.104 v1(78.754,92.498)
MCU_CTS: CN1.6 U2.15 | length 6
  Top Layer w0.25: U2.15@77.661,97.522 80.476,97.522 v1(80.786,97.832)
  Bottom Layer w0.25: v1(80.786,97.832) 81.916,97.832 CN1.6
MCU_DCD: CN1.7 U2.14 | length 4
  Top Layer w0.25: U2.14@77.661,98.172 v1(79.516,98.172)
  Bottom Layer w0.25: CN1.7 79.008,99.229 79.643,98.594 79.643,98.299 v1(79.516,98.172)
MCU_DTR: CN1.4 U2.17 | length 6.7
  Top Layer w0.25: U2.17@77.661,96.222 80.618,96.222 v1(80.786,96.054)
  Bottom Layer w0.25: v1(80.786,96.054) 80.786,95.222 81.859,94.149 CN1.4
MCU_RI: CN1.8 U2.13 | length 5.7
  Top Layer w0.25: U2.13@77.661,98.822 80.558,98.822 v1(80.659,98.721)
  Bottom Layer w0.25: v1(80.659,98.721) 81.167,99.229 CN1.8
MCU_RTS: CN1.5 U2.16 | length 5.2
  Top Layer w0.25: U2.16@77.661,96.872 78.782,96.872 78.838,96.816 v1(80.532,96.816)
  Bottom Layer w0.25: CN1.5 78.386,96.816 v1(80.532,96.816)
MCU_RXD: CN1.2 U2.20 | length 7.4
  Top Layer w0.25: U2.20@77.661,94.272 v1(80.659,94.272)
  Bottom Layer w0.25: v1(80.659,94.272) 80.659,92.809 81.859,91.609 CN1.2
MCU_TXD: CN1.3 U2.18 | length 5.4
  Top Layer w0.25: U2.18@77.661,95.572 79.998,95.572 v1(80.024,95.546)
  Bottom Layer w0.25: CN1.3 78.559,93.849 79.085,93.849 79.262,94.026 79.262,94.784 v1(80.024,95.546)
NW: Q3.1 U3.6 | length 6.2
  Top Layer w0.25: Q3.1@92.457,82.349 95.529,82.349 96.784,83.604 U3.6@96.784,85.003
NW_MODE: Q5.1 U3.5 | length 9.6
  Top Layer w0.25: Q5.1@88.27,81.464 88.397,81.591 88.397,81.627 89.648,82.878 94.788,82.878 95.611,83.701 95.611,84.876 U3.5@95.484,85.003
PKEY: pad.1@121.172,85.64 Q1.1 | length 5.7
  Top Layer w0.25: Q1.1@118.54,80.941 118.763,81.164 118.763,81.453 v1(119.013,81.703)
  Bottom Layer w0.25: v1(119.013,81.703) 119.013,83.481 120.857,85.325 pad.1@120.857,85.64
PWRKEY: C14.2 Q1.3 U3.21 | length 18.5
  Top Layer w0.25: U3.21@117.134,93.803 117.388,94.057 119.105,94.057 119.775,93.387 119.775,80.696 120.038,80.433 120.038,80.306 119.967,80.235 C14.2
RF_ANT: C22.2 R9.1 U3.49 | length 5.2
  Top Layer w0.8: R9.1@95.899,119.93 96.04,119.789 96.04,121.256 ccw(c95.992,121.256) C22.2 ; 96.294,119.789 cw(c94.498,117.993) 97.038,117.993 U3.49@97.038,116.503
RKEY: pad.1@121.172,88.18 Q2.1 | length 11.7
  Top Layer w0.25: v1(114.015,81.576) 114.142,81.449 Q2.1
  Bottom Layer w0.25: v1(114.015,81.576) 115.838,81.576 118.124,83.862 118.124,84.142 118.124,85.513 120.791,88.18 pad.1@120.857,88.18
RSTKEY: D2.1 Q2.3 RST.2 U3.20 | length 23.9
  Top Layer w0.25: D2.1 113.882,80.509 114.314,80.941 Q2.3 116.863,80.941 116.981,81.059 v1(116.981,81.703) 119.14,83.862 119.14,92.253 118.89,92.503 U3.20@117.134,92.503 ; RST.2 116.981,77.919 v1(116.981,77.004)
  Bottom Layer w0.25: v1(116.981,77.004) 117.314,77.337 117.314,81.37 v1(116.981,81.703)
SIM_CLK: C12.2 CARD1.C3 D3.5 U3.16 | length 31.1
  Top Layer w0.25: v1(104.662,77.893) 105.08,78.311 C12.2 105.424,78.436 106.059,79.071 D3.5 ; v1(112.663,82.592) 112.663,83.282 113.171,83.79 113.171,84.716 U3.16@112.884,85.003
  Bottom Layer w0.25: v1(104.662,77.893) 104.789,78.02 104.916,78.02 107.509,80.613 110.557,80.613 112.536,82.592 v1(112.663,82.592) 113.044,82.973 113.044,92.371 112.282,93.133 110.504,93.133 109.619,92.248 CARD1.C3@109.619,90.915
SIM_DATA: C15.2 CARD1.C7 D3.6 R6.2 U3.15 | length 21.6
  Top Layer w0.25: D3.6 106.821,80.006 106.821,78.453 108.076,78.453 R6.2@108.091,78.438 ; R6.2 108.218,79.671 v1(109.996,81.449) ; U3.15@111.584,85.003 111.774,84.813 111.774,82.846 v1(111.647,82.719)
  Bottom Layer w0.25: CARD1.C7@108.349,90.915 108.599,90.665 108.599,89.704 111.901,86.402 111.901,82.973 ; v1(109.996,81.449) 111.52,82.973 111.901,82.973 ; v1(111.647,82.719) 111.901,82.973
SIM_DET: CARD1.CD D3.1 R5.2 U3.13 | length 16.8
  Top Layer w0.25: D3.1 108.082,82.018 R5.2 108.091,82.022 109.361,83.292 v1(109.361,83.354) 109.361,84.626 U3.13@108.984,85.003
  Bottom Layer w0.25: CARD1.CD 102.573,90.661 102.63,90.604 102.63,89.704 102.884,89.45 104.154,89.45 109.361,84.243 v1(109.361,83.354)
SIM_GND: C11.2 CARD1.C5 U3.10 | length 18.9
  Top Layer w0.25: C11.2 103.683,82.375 v1(104.662,83.354) 105.084,83.776 U3.10@105.084,85.003
  Bottom Layer w0.25: CARD1.C5@103.44,91.086 103.44,92.587 103.148,92.879 101.741,92.879 100.725,91.863 100.725,90.212 104.662,86.275 v1(104.662,83.354)
SIM_RST: C13.2 CARD1.C2 D3.4 U3.17 | length 39.4
  Top Layer w0.25: v1(103.9,77.258) 103.9,77.856 C13.2 104.117,78.364 104.662,78.909 104.662,79.371 D3.4 ; U3.17@114.184,85.003 114.314,84.873 114.314,83.354 v1(114.695,82.973)
  Bottom Layer w0.25: v1(103.9,77.258) 105.17,77.258 108.091,80.179 111.393,80.179 113.933,82.719 113.933,83.354 ; CARD1.C2@107.079,90.915 106.952,91.042 106.952,92.375 108.593,94.016 112.415,94.016 113.806,92.625 113.806,83.481 113.933,83.354 ; v1(114.695,82.973) 114.314,82.973 113.933,83.354
SIM_VDD: C11.1 CARD1.C1 D3.3 R6.1 U3.14 | length 29.9
  Top Layer w0.25: C11.1 104.676,81.285 D3.3 105.409,82.577 105.805,82.973 v1(107.837,82.973) ; R6.1 109.817,77.46 111.266,78.909 111.266,81.83 110.504,82.592 v1(110.504,82.973) 110.504,84.783 U3.14@110.284,85.003
  Bottom Layer w0.25: CARD1.C1@104.539,90.915 104.539,90.665 110.504,84.7 v1(110.504,82.973) 110.504,82.719 110.123,82.338 108.472,82.338 v1(107.837,82.973)
SLEEP_IND: U3.3
STATUS: Q4.1 U3.61 | length 40.7
  Top Layer w0.25: v1(86.628,104.69) 87.441,105.503 U3.61@88.634,105.503
  Top Layer w0.35: Q4.1 85.713,81.418 86.78,81.418 v1(87.771,82.409)
  Bottom Layer w0.25: v1(86.628,104.69) 92.47,104.69 95.518,101.642 95.518,84.574 93.353,82.409 v1(87.771,82.409)
USB_DM: L3.4 U3.70 | length 8.5
  Top Layer w0.25: v1(86.628,93.387) 86.628,93.514 86.917,93.803 U3.70@88.634,93.803
  Top Layer w0.35: v1(84.85,90.466) 84.85,89.95 85.339,89.462 L3.4
  Bottom Layer w0.25: v1(84.85,90.466) 85.358,90.974 85.358,92.879 85.866,93.387 v1(86.628,93.387)
USB_DP: L3.3 U3.69 | length 9.3
  Top Layer w0.25: L3.3 86.12,88.592 86.12,90.289 85.358,91.051 85.358,93.768 86.439,94.849 87.999,94.849 88.253,95.103 U3.69@88.634,95.103
VBAT: C1.1 C2.1 C4.1 C5.1 C7.1 C8.1 C9.1 C10.1 Cout1.2 Cout2.2 D1.1 NM.2 NS.1 Rfbt1.2 S.2 U1.3 U3.57 U3.58 U3.59 U3.60 | length 68.8
  Top Layer w0.25: NS.1@92.812,77.131 NS.1
  Top Layer w0.8: S.2 85.288,77.094 85.326,77.131 92.812,77.131 95.391,77.131 97.423,79.163 v1(97.423,80.306)
  Bottom Layer w1: 88.082,109.897 96.915,110.024 99.201,112.31 99.201,112.818
  Bottom Layer w1.5: 86.171,109.897 88.082,109.897 93.867,109.897 97.042,106.722 97.042,79.099
  Bottom Layer w2: 85.104,109.897 86.171,109.897
  other v1: 97.423,79.468 85.104,109.233 86.171,109.233 85.104,110.249 86.171,110.249
VBUS: U3.71 USBC1.A4 USBC1.A9 USBC1.B4 USBC1.B9 | length 19.4
  Top Layer w0.25: USBC1.A9@83.641,82.328 83.339,82.63 81.383,82.63 80.659,83.354 80.659,86.402 81.04,86.783 82.437,86.783 82.955,87.301 83.641,87.301 83.701,87.241 84.75,87.241 85.143,87.633 86.462,87.633 86.755,87.926 86.755,91.99 87.268,92.503 U3.71@88.634,92.503
VCC(5V): Cin1.2 L1.1 PWR.1 U1.5 U1.7 | length 5.7
  Top Layer w0.25: 77.992,123.236 77.992,124.252 78.242,124.502 Cin1.2@79.024,124.502 ; U1.5 82.433,119.672 v1(82.818,120.057)
  Bottom Layer w0.25: v1(80.405,119.676) 80.786,120.057 v1(82.818,120.057)
VDD_EXT: C3.2 C24.2 C26.1 R2.2 R5.1 R14.2 R15.1 U2.2 U3.7 | length 98.1
  Top Layer w0.25: v1(81.167,102.658) 80.786,102.658 79.845,101.717 R2.2 79.845,100.868 79.897,100.816 79.897,99.864 80.278,99.483 81.167,99.483 81.548,99.102 81.548,95.211 ; C3.2 82.056,93.387 81.548,93.895 81.548,95.211 ; U2.2@83.403,94.922 81.837,94.922 81.548,95.211 ; C24.2 99.771,80.879 v1(100.217,80.433) ; v1(107.329,81.195) 108.039,81.195 R5.1
  Top Layer w0.8: v1(95.391,81.449) ccw(c93.427,91.015) 98.084,82.431
  Top Layer w1: 98.084,82.439 98.439,82.084 C24.2 ; 98.338,82.439 U3.7@98.338,85.003
  Bottom Layer w0.25: v1(100.217,80.433) 103.9,80.433 104.662,81.195 v1(107.329,81.195)
  Bottom Layer w0.35: R14.2 91.454,90.137 R15.1
  Bottom Layer w0.5: 86.851,91.451 87.6,91.451 R14.2
  Bottom Layer w0.8: v1(81.167,102.658) 81.802,102.023 85.139,102.023 ; v1(95.391,81.449) 86.755,81.449 86.12,82.084 86.12,90.72 86.851,91.451 87.898,92.498 87.898,99.61 85.485,102.023 85.139,102.023 ; 96.788,112.691 84.342,112.691 82.31,110.659 82.31,104.852 85.139,102.023
WAKEUP_IN: C25.2 Q6.3 U3.1 | length 5.6
  Top Layer w0.35: v1(89.422,86.275) 89.422,85.865 U3.1@90.284,85.003
  Bottom Layer w0.35: v1(89.422,86.275) 89.422,85.204 C25.2 91.412,84.845 Q6.3@91.962,85.395
WAKEUP_IN_MCU: Q6.1 | length 2.3
  Bottom Layer w0.35: Q6.1 93.037,84.024 94.272,85.259
WIFI/BT_ANT: C23.2 R10.1 U3.35 | length 10.1
  Top Layer w0.5: C23.2 119.426,118.104 ccw(c119.426,118.957) R10.1
  Top Layer w0.8: U3.35@117.134,112.13 118.114,112.13 ccw(c118.114,114.479) 119.529,112.604 ; 119.775,112.818 cw(c118.114,114.479) 119.529,112.604 ; R10.1@120.029,118.227 120.029,113.304 cw(c119.289,113.304) 119.529,112.604
pads on no net: CARD1.C6 U3.4 U3.11 U3.12 U3.18 U3.23 U3.24 U3.25 U3.26 U3.27 U3.28 U3.29 U3.30 U3.31 U3.32 U3.33 U3.34 U3.37 U3.38 U3.39 U3.40 U3.43 U3.55 U3.73 U3.74 U3.75 U3.77 U3.78 U3.79 U3.80 U3.81 U3.82 U3.83 U3.84 U3.113 U3.114 U3.115 U3.116 U3.117 U3.118 U3.119 U3.120 U3.121 U3.122 U3.123 U3.124 U3.125 U3.126 U3.127 U3.128 U3.129 U3.130 U3.131 U3.132 U3.133 U3.134 U3.135 U3.136 U3.137 U3.138 U3.139 U3.140 U3.141 U3.142 U3.143 U3.144 USBC1.0 USBC1.1 USBC1.2 USBC1.3 USBC1.A5 USBC1.A8 USBC1.B5 USBC1.B8

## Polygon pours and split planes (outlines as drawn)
GND on Top Layer (solid, remove dead copper, pour order 0): 87.476,118.956 112.028,118.956 112.028,115.104 87.476,115.104
GND on Bottom Layer (solid, remove dead copper, pour order 6): 84.721,125.835 84.773,125.826 121.045,126.033 121.045,76.432 76.722,76.432 76.595,76.559 76.595,125.835
GND on Top Layer (solid, remove dead copper, pour order 2): 84.723,125.899 84.723,119.422 87.39,119.422 87.517,119.549 87.898,119.168 87.898,115.231 88.152,114.977 114.695,114.977 115.203,114.469 115.203,110.278 120.791,110.278 120.918,110.405 120.918,125.772 120.791,125.772 120.664,125.899
GND on Top Layer (solid, remove dead copper, pour order 4): 76.468,125.899 84.596,125.899 84.723,125.772 84.723,119.803 84.596,119.676 87.517,119.676 87.771,119.422 87.771,115.612 87.644,115.485 87.644,115.098 120.918,115.098 120.918,76.496 76.595,76.496 76.468,76.623

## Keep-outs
Board Outline Layer:
  lines w0.254: 76.261,76.2 121.261,76.2 121.261,126.2 76.261,126.2 76.261,76.2

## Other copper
Top Layer:
  region net VBAT: 76.645,111.403 79.528,111.403 80.33,110.601 80.347,110.601 80.405,110.659 84.211,110.659 84.667,110.203 89.676,110.203 89.676,106.425 84.783,106.307 84.723,106.247 84.723,106.214 83.942,106.995 83.942,108.1 83.453,108.833 83.326,109.008 80.191,109.008 80.191,107.503 76.614,107.503 76.595,107.484 76.468,107.611 76.468,111.226
  region net VBAT: 84.27,112.784 84.27,109.444 84.215,109.389 87.009,109.389 87.39,109.008 89.93,109.008 89.93,111.04 86.628,111.04 86.501,111.167 86.501,116.056 86.291,116.266 84.196,116.266 84.088,116.374 84.088,112.966
  region net VBAT: 80.786,105.452 80.786,104.436 80.913,104.309 85.348,104.309 85.348,106.595 84.469,106.595 84.342,106.722 84.342,105.415 80.823,105.415
  region net VBAT: 82.535,118.279 82.535,116.651 82.818,115.358 82.818,112.126 85.993,112.126 85.993,116.386 84.749,116.386 84.749,117.345 83.498,117.345 83.453,117.39 83.453,118.152 83.326,118.279
  region net $1N56747: 76.603,118.033 76.603,115.739 80.754,115.739 80.754,118.033
  region net VCC(5V): 76.754,119.22 80.584,119.22 80.659,119.295 81.084,118.87 81.562,118.87 81.562,119.385 80.382,120.565 80.278,120.565 79.77,121.073 79.77,123.486 79.389,123.867 76.722,123.867 76.722,119.252
  region net GND: 80.532,123.359 82.31,123.359 82.31,120.057 81.557,120.057 80.668,120.946 80.405,120.946 80.405,123.232
Bottom Layer:
  region net WAKEUP_IN_MCU: 94.725,85.281 cw(c94.025,85.281) 93.325,85.281 cw(c94.025,85.281)
  region net AP_READY_MCU: 94.725,87.759 cw(c94.025,87.759) 93.325,87.759 cw(c94.025,87.759)
  region net ADC1: 107.434,112.849 cw(c106.734,112.849) 106.034,112.849 cw(c106.734,112.849)
  region net I2C_SCL: 112.443,112.818 cw(c111.743,112.818) 111.043,112.818 cw(c111.743,112.818)
  region net I2C_SDA: 109.965,112.818 cw(c109.265,112.818) 108.565,112.818 cw(c109.265,112.818)
  region net VDD_EXT: 97.401,112.82 cw(c96.701,112.82) 96.001,112.82 cw(c96.701,112.82)
  region net VBAT: 99.933,112.833 cw(c99.233,112.833) 98.533,112.833 cw(c99.233,112.833)
  region net GND: 102.463,112.803 cw(c101.763,112.803) 101.063,112.803 cw(c101.763,112.803)
  region net ADC0: 104.941,112.803 cw(c104.241,112.803) 103.541,112.803 cw(c104.241,112.803)

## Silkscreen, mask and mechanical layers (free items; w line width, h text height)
Bottom Silkscreen Layer:
  text "5v" at 79.08,118.187 h1.2
  text "GND" at 82.776,118.01 h1.2
  text "VBAT" at 100.471,110.913 h1.2
  text "SCL" at 113.132,110.821 h1.2
  text "VDD_EXT" at 97.169,110.786 h1.2
  text "GND" at 103.011,110.786 h1.2
  text "A0" at 104.916,110.786 h1.2
  text "A1" at 107.456,110.786 h1.2
  text "SDA" at 110.377,110.786 h1.2
  text "DCD" at 78.754,100.626 h1.2
  text "RI" at 85.612,99.737 h1.2
  text "RTS" at 78.754,97.324 h1.2
  text "CTS" at 85.612,97.197 h1.2
  text "Tx" at 77.912,94.819 h1.2
  text "DTR" at 85.739,94.784 h1.2
  text "VD" at 77.992,92.371 h1.2
  text "Rx" at 84.85,92.117 h1.2
  text "GND" at 119.521,89.958 h1.5
  text "AP_R" at 98.185,87.418 h1.2
  text "RST" at 119.585,87.176 h1.5
  text "Wake" at 97.931,84.878 h1.2
  text "PKEY" at 119.458,84.547 h1.5
Bottom Solder Mask Layer:
  region: 94.725,87.759 cw(c94.025,87.759) 93.325,87.759 cw(c94.025,87.759)
  region: 94.725,85.281 cw(c94.025,85.281) 93.325,85.281 cw(c94.025,85.281)
  region: 97.401,112.82 cw(c96.701,112.82) 96.001,112.82 cw(c96.701,112.82)
  region: 99.933,112.833 cw(c99.233,112.833) 98.533,112.833 cw(c99.233,112.833)
  region: 102.463,112.803 cw(c101.763,112.803) 101.063,112.803 cw(c101.763,112.803)
  region: 104.941,112.803 cw(c104.241,112.803) 103.541,112.803 cw(c104.241,112.803)
  region: 107.434,112.849 cw(c106.734,112.849) 106.034,112.849 cw(c106.734,112.849)
  region: 109.965,112.818 cw(c109.265,112.818) 108.565,112.818 cw(c109.265,112.818)
  region: 112.443,112.818 cw(c111.743,112.818) 111.043,112.818 cw(c111.743,112.818)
